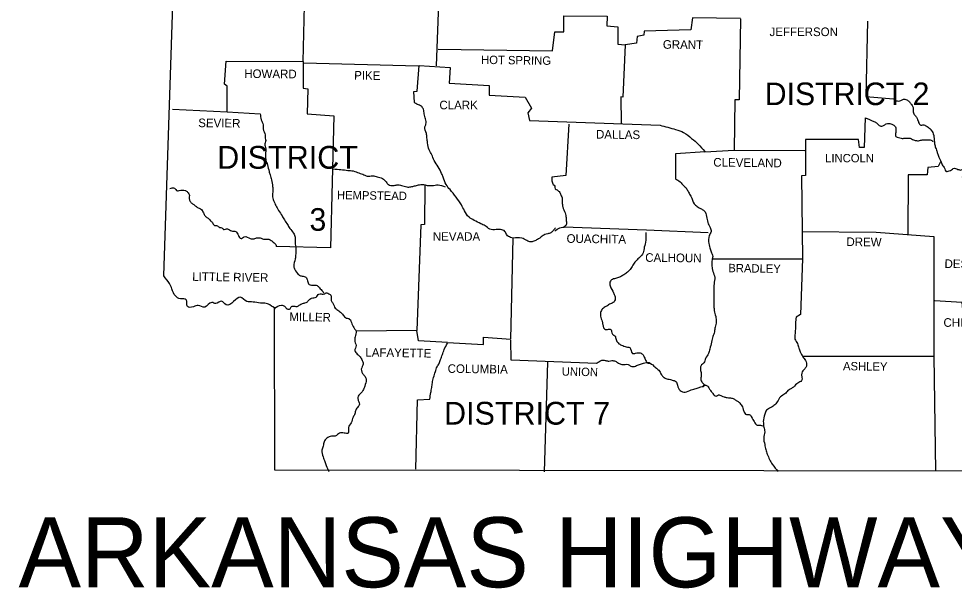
# Model space of a CAD drawing. Extents: x 1096785 to 1382432, y 216169 to 341661.
# Drawn here: x 1227896 to 1237243, y 280666 to 286360 of the extents above; entities that cross this region are included whole.
import ezdxf

# ---------------------------------------------------------------- set-up
doc = ezdxf.new("R2010")
doc.units = 0
for name, color, linetype in [('1', 7, 'Continuous'), ('21', 7, 'Continuous'), ('3', 7, 'Continuous')]:
    doc.layers.add(name, color=color, linetype=linetype)

msp = doc.modelspace()

# ---------------------------------------------------------------- linework, layer by layer
at = {"layer": '1'}
for points in [[(1229345.2, 283788.3), (1229525.2, 289214.3), (1229111.2, 292538.3)], [(1232071.2, 285890.3), (1232117.2, 287136.3)], [(1229431.2, 285454.3), (1229977.2, 285430.3), (1229979.2, 285686.3), (1229951.2, 285706.3), (1229969.2, 285934.3), (1230739.2, 285932.3), (1230761.2, 286916.3)], [(1232085.2, 286056.3), (1233229.2, 286040.3), (1233251.2, 286230.3), (1233341.2, 286230.3), (1233343.2, 286390.3), (1233775.2, 286384.3), (1233771.2, 286288.3), (1233883.2, 286280.3), (1233883.2, 286104.3), (1233955.2, 286098.3)], [(1235107.2, 286362.3), (1234629.2, 286370.3), (1234611.2, 286248.3), (1234145.2, 286234.3), (1234141.2, 286194.3), (1234075.2, 286182.3), (1234067.2, 286114.3), (1233955.2, 286098.3)], [(1235107.2, 286358.3), (1235095.2, 285550.3), (1235049.2, 285548.3), (1235043.2, 285046.3)], [(1236375.2, 286336.3), (1236359.2, 285582.3), (1236637.2, 285560.3)], [(1233955.2, 286098.3), (1233931.2, 285574.3), (1233913.2, 285580.3), (1233915.2, 285308.3)], [(1230739.2, 285932.3), (1230739.2, 285666.3), (1230783.2, 285658.3), (1230779.2, 285410.3), (1231043.2, 285390.3), (1231011.2, 284068.3), (1230467.2, 284082.3)], [(1230743.2, 285918.3), (1231887.2, 285888.3)], [(1231849.2, 285522.3), (1231845.2, 285632.3), (1231877.2, 285634.3), (1231897.2, 285892.3), (1232205.2, 285872.3), (1232197.2, 285714.3), (1232595.2, 285692.3), (1232597.2, 285596.3), (1232957.2, 285574.3), (1233019.2, 285466.3), (1232981.2, 285418.3), (1232999.2, 285344.3), (1234303.2, 285296.3)], [(1229977.2, 285430.3), (1230309.2, 285410.3)], [(1236353.2, 285368.3), (1236341.2, 285074.3), (1236295.2, 285074.3), (1236287.2, 285152.3), (1235755.2, 285152.3), (1235755.2, 285040.3)], [(1233391.2, 285306.3), (1233361.2, 284792.3), (1233223.2, 284776.3)], [(1234755.2, 285028.3), (1234459.2, 285010.3), (1234457.2, 284760.3)], [(1234751.2, 285028.3), (1235043.2, 285046.3)], [(1235043.2, 285046.3), (1235751.2, 285042.3)], [(1235755.2, 285042.3), (1235757.2, 284792.3), (1235715.2, 284790.3), (1235727.2, 283960.3)], [(1237107.2, 284936.3), (1237083.2, 284882.3), (1236977.2, 284872.3), (1236971.2, 284800.3), (1236781.2, 284800.3), (1236779.2, 284202.3)], [(1231955.2, 284700.3), (1231951.2, 284302.3), (1231915.2, 284298.3), (1231875.2, 283244.3)], [(1233341.2, 284278.3), (1234169.2, 284248.3), (1234783.2, 284224.3)], [(1232179.2, 283124.3), (1232539.2, 283102.3), (1232541.2, 283176.3), (1232811.2, 283158.3), (1232837.2, 284166.3)], [(1235721.2, 284232.3), (1236463.2, 284226.3), (1237039.2, 284182.3)], [(1237039.2, 284182.3), (1237039.2, 282986.3), (1237055.2, 281836.3)], [(1234823.2, 283958.3), (1235727.2, 283960.3)], [(1235727.2, 283960.3), (1235707.2, 283404.3), (1235663.2, 283376.3)], [(1237049.2, 283544.3), (1237317.2, 283528.3), (1237329.2, 283412.3), (1237571.2, 283420.3), (1237581.2, 283518.3), (1237627.2, 283518.3)], [(1237785.2, 281836.3), (1230455.2, 281848.3), (1230451.2, 283466.3)], [(1232179.2, 283124.3), (1231889.2, 283140.3), (1231875.2, 283244.3), (1231269.2, 283238.3)], [(1233669.2, 282914.3), (1232815.2, 282946.3), (1232811.2, 283148.3)], [(1235727.2, 282988.3), (1237039.2, 282988.3)], [(1233179.2, 282928.3), (1233147.2, 281830.3)], [(1231865.2, 281858.3), (1231879.2, 282550.3), (1232003.2, 282558.3)]]:
    msp.add_lwpolyline(points, dxfattribs=at)
for points in [[(1236637.2, 285560.3), (1236667.2, 285540.3), (1236709.2, 285542.3), (1236737.2, 285554.3), (1236759.2, 285552.3), (1236789.2, 285534.3), (1236809.2, 285510.3), (1236823.2, 285492.3), (1236833.2, 285464.3), (1236833.2, 285438.3), (1236843.2, 285402.3), (1236855.2, 285388.3), (1236871.2, 285362.3), (1236881.2, 285338.3), (1236887.2, 285322.3), (1236909.2, 285296.3), (1236929.2, 285298.3), (1236947.2, 285296.3), (1236971.2, 285282.3), (1237007.2, 285254.3), (1237013.2, 285246.3), (1237037.2, 285194.3), (1237041.2, 285162.3), (1237045.2, 285120.3), (1237053.2, 285080.3), (1237069.2, 285036.3), (1237077.2, 285006.3), (1237095.2, 284964.3), (1237107.2, 284936.3), (1237123.2, 284900.3), (1237147.2, 284860.3), (1237157.2, 284836.3), (1237191.2, 284838.3), (1237215.2, 284848.3), (1237233.2, 284864.3), (1237255.2, 284862.3), (1237279.2, 284854.3), (1237311.2, 284848.3), (1237331.2, 284860.3), (1237341.2, 284868.3), (1237343.2, 284886.3), (1237361.2, 284896.3), (1237381.2, 284882.3), (1237403.2, 284850.3), (1237403.2, 284830.3), (1237395.2, 284818.3), (1237369.2, 284802.3), (1237333.2, 284790.3), (1237323.2, 284776.3), (1237357.2, 284760.3), (1237411.2, 284756.3), (1237425.2, 284768.3), (1237461.2, 284758.3), (1237475.2, 284768.3), (1237523.2, 284766.3), (1237545.2, 284782.3), (1237589.2, 284780.3), (1237603.2, 284770.3), (1237603.2, 284752.3), (1237639.2, 284744.3), (1237665.2, 284750.3), (1237699.2, 284740.3), (1237729.2, 284724.3), (1237745.2, 284702.3), (1237765.2, 284678.3), (1237783.2, 284684.3), (1237797.2, 284702.3), (1237827.2, 284734.3), (1237827.2, 284754.3), (1237835.2, 284768.3), (1237845.2, 284788.3)], [(1232837.2, 284166.3), (1232809.2, 284174.3), (1232773.2, 284198.3), (1232753.2, 284234.3), (1232711.2, 284252.3), (1232665.2, 284252.3), (1232603.2, 284256.3), (1232555.2, 284290.3), (1232513.2, 284310.3), (1232447.2, 284344.3), (1232395.2, 284376.3), (1232349.2, 284440.3), (1232319.2, 284498.3), (1232265.2, 284576.3), (1232205.2, 284652.3), (1232167.2, 284702.3), (1232137.2, 284776.3), (1232121.2, 284812.3), (1232087.2, 284880.3), (1232047.2, 284942.3), (1232023.2, 285000.3), (1231997.2, 285048.3), (1231981.2, 285118.3), (1231975.2, 285170.3), (1231969.2, 285214.3), (1231953.2, 285278.3), (1231965.2, 285306.3), (1231961.2, 285358.3), (1231947.2, 285408.3), (1231939.2, 285454.3), (1231919.2, 285484.3), (1231881.2, 285502.3), (1231849.2, 285522.3)], [(1230309.2, 285410.3), (1230319.2, 285350.3), (1230337.2, 285298.3), (1230339.2, 285258.3), (1230357.2, 285198.3), (1230357.2, 285176.3), (1230363.2, 285132.3), (1230355.2, 285108.3), (1230365.2, 285060.3), (1230363.2, 285024.3), (1230363.2, 284994.3), (1230365.2, 284944.3), (1230381.2, 284900.3), (1230397.2, 284834.3), (1230407.2, 284800.3), (1230423.2, 284748.3), (1230433.2, 284684.3), (1230435.2, 284636.3), (1230431.2, 284592.3), (1230443.2, 284542.3), (1230465.2, 284492.3), (1230493.2, 284444.3), (1230527.2, 284390.3), (1230551.2, 284348.3), (1230581.2, 284302.3), (1230605.2, 284264.3), (1230641.2, 284216.3), (1230657.2, 284176.3), (1230657.2, 284120.3), (1230665.2, 284068.3), (1230663.2, 284010.3), (1230659.2, 283958.3), (1230645.2, 283886.3), (1230655.2, 283852.3), (1230693.2, 283802.3), (1230717.2, 283788.3), (1230759.2, 283780.3), (1230779.2, 283752.3), (1230791.2, 283710.3), (1230833.2, 283696.3), (1230879.2, 283692.3), (1230901.2, 283668.3), (1230931.2, 283636.3), (1230941.2, 283620.3)], [(1236353.2, 285368.3), (1236389.2, 285356.3), (1236415.2, 285342.3), (1236449.2, 285330.3), (1236471.2, 285314.3), (1236501.2, 285288.3), (1236537.2, 285292.3), (1236563.2, 285308.3), (1236589.2, 285312.3), (1236609.2, 285310.3), (1236631.2, 285298.3), (1236655.2, 285280.3), (1236659.2, 285254.3), (1236659.2, 285224.3), (1236659.2, 285182.3), (1236673.2, 285176.3), (1236723.2, 285164.3), (1236757.2, 285166.3), (1236789.2, 285166.3), (1236815.2, 285160.3), (1236837.2, 285148.3), (1236853.2, 285144.3), (1236877.2, 285140.3), (1236897.2, 285142.3), (1236931.2, 285150.3), (1236951.2, 285150.3), (1236983.2, 285150.3), (1237003.2, 285148.3), (1237033.2, 285132.3)], [(1234303.2, 285296.3), (1234459.2, 285252.3), (1234539.2, 285222.3), (1234619.2, 285164.3), (1234685.2, 285106.3), (1234751.2, 285032.3)], [(1231039.2, 284858.3), (1231115.2, 284852.3), (1231185.2, 284844.3), (1231239.2, 284838.3), (1231295.2, 284818.3), (1231345.2, 284800.3), (1231377.2, 284786.3), (1231431.2, 284790.3), (1231477.2, 284780.3), (1231529.2, 284762.3), (1231567.2, 284728.3), (1231591.2, 284702.3), (1231637.2, 284692.3), (1231675.2, 284698.3), (1231721.2, 284694.3), (1231773.2, 284678.3), (1231815.2, 284680.3), (1231849.2, 284688.3), (1231889.2, 284698.3), (1231939.2, 284702.3), (1231977.2, 284694.3), (1232027.2, 284692.3), (1232085.2, 284698.3), (1232157.2, 284678.3)], [(1233223.2, 284776.3), (1233223.2, 284738.3), (1233237.2, 284702.3), (1233251.2, 284686.3), (1233257.2, 284660.3), (1233275.2, 284648.3), (1233301.2, 284624.3), (1233315.2, 284590.3), (1233325.2, 284568.3), (1233325.2, 284540.3), (1233327.2, 284512.3), (1233331.2, 284478.3), (1233355.2, 284418.3), (1233361.2, 284394.3), (1233365.2, 284374.3), (1233367.2, 284340.3), (1233367.2, 284300.3), (1233341.2, 284278.3)], [(1234457.2, 284760.3), (1234503.2, 284730.3), (1234541.2, 284690.3), (1234569.2, 284660.3), (1234587.2, 284626.3), (1234611.2, 284586.3), (1234645.2, 284510.3), (1234675.2, 284484.3), (1234717.2, 284458.3), (1234743.2, 284440.3), (1234769.2, 284382.3), (1234781.2, 284324.3), (1234803.2, 284272.3), (1234813.2, 284232.3), (1234795.2, 284192.3), (1234791.2, 284112.3), (1234803.2, 284058.3), (1234819.2, 284018.3), (1234829.2, 283972.3), (1234823.2, 283958.3)], [(1229407.2, 284664.3), (1229451.2, 284666.3), (1229481.2, 284640.3), (1229499.2, 284642.3), (1229531.2, 284646.3), (1229561.2, 284644.3), (1229583.2, 284626.3), (1229601.2, 284594.3), (1229599.2, 284564.3), (1229601.2, 284552.3), (1229615.2, 284526.3), (1229639.2, 284506.3), (1229665.2, 284486.3), (1229689.2, 284470.3), (1229729.2, 284444.3), (1229733.2, 284436.3), (1229749.2, 284404.3), (1229769.2, 284378.3), (1229793.2, 284362.3), (1229819.2, 284334.3), (1229831.2, 284322.3), (1229851.2, 284294.3), (1229873.2, 284292.3), (1229903.2, 284274.3), (1229925.2, 284268.3), (1229949.2, 284252.3), (1229973.2, 284260.3), (1230003.2, 284248.3), (1230043.2, 284236.3), (1230065.2, 284232.3), (1230091.2, 284194.3), (1230117.2, 284162.3), (1230149.2, 284180.3), (1230209.2, 284162.3), (1230247.2, 284160.3), (1230281.2, 284170.3), (1230307.2, 284168.3), (1230355.2, 284156.3), (1230385.2, 284156.3), (1230417.2, 284144.3), (1230447.2, 284120.3), (1230467.2, 284094.3), (1230467.2, 284082.3)], [(1233259.2, 284268.3), (1233237.2, 284242.3), (1233211.2, 284220.3), (1233181.2, 284210.3), (1233153.2, 284202.3), (1233117.2, 284178.3), (1233089.2, 284158.3), (1233051.2, 284140.3), (1233015.2, 284128.3), (1232971.2, 284142.3), (1232947.2, 284156.3), (1232921.2, 284166.3), (1232837.2, 284166.3)], [(1233251.2, 284236.3), (1233303.2, 284270.3), (1233361.2, 284278.3)], [(1234161.2, 284224.3), (1234157.2, 284124.3), (1234143.2, 284062.3), (1234129.2, 284006.3), (1234099.2, 283974.3), (1234067.2, 283942.3), (1234037.2, 283906.3), (1234011.2, 283862.3), (1233985.2, 283834.3), (1233951.2, 283806.3), (1233917.2, 283786.3), (1233879.2, 283768.3), (1233837.2, 283758.3), (1233807.2, 283736.3), (1233805.2, 283688.3), (1233839.2, 283620.3), (1233851.2, 283588.3), (1233855.2, 283550.3), (1233841.2, 283528.3), (1233809.2, 283510.3), (1233771.2, 283488.3), (1233737.2, 283468.3), (1233713.2, 283434.3), (1233709.2, 283388.3), (1233725.2, 283334.3), (1233731.2, 283302.3), (1233757.2, 283252.3), (1233777.2, 283254.3), (1233813.2, 283252.3), (1233817.2, 283242.3), (1233819.2, 283232.3), (1233827.2, 283206.3), (1233857.2, 283184.3), (1233861.2, 283164.3), (1233879.2, 283126.3), (1233909.2, 283100.3), (1233931.2, 283092.3), (1233977.2, 283078.3), (1234001.2, 283072.3), (1234027.2, 283014.3), (1234059.2, 283016.3), (1234083.2, 283020.3), (1234123.2, 283010.3), (1234141.2, 282986.3), (1234159.2, 282946.3), (1234183.2, 282918.3), (1234199.2, 282918.3)], [(1234823.2, 283958.3), (1234831.2, 283834.3), (1234849.2, 283774.3), (1234843.2, 283710.3), (1234841.2, 283648.3), (1234841.2, 283592.3), (1234841.2, 283538.3), (1234841.2, 283482.3), (1234845.2, 283442.3), (1234859.2, 283384.3), (1234865.2, 283330.3), (1234853.2, 283278.3), (1234847.2, 283230.3), (1234831.2, 283182.3), (1234817.2, 283128.3), (1234801.2, 283058.3), (1234787.2, 283012.3), (1234759.2, 282964.3), (1234741.2, 282920.3), (1234713.2, 282892.3), (1234709.2, 282844.3), (1234715.2, 282800.3), (1234711.2, 282760.3), (1234725.2, 282722.3), (1234761.2, 282696.3)], [(1230451.2, 283466.3), (1230459.2, 283462.3), (1230421.2, 283488.3), (1230369.2, 283514.3), (1230311.2, 283518.3), (1230237.2, 283528.3), (1230175.2, 283534.3), (1230111.2, 283576.3), (1230043.2, 283532.3), (1229967.2, 283500.3), (1229923.2, 283536.3), (1229865.2, 283512.3), (1229825.2, 283524.3), (1229755.2, 283476.3), (1229689.2, 283494.3), (1229641.2, 283480.3), (1229581.2, 283482.3), (1229569.2, 283550.3), (1229511.2, 283560.3), (1229461.2, 283588.3), (1229427.2, 283658.3), (1229403.2, 283712.3), (1229345.2, 283788.3)], [(1230451.2, 283466.3), (1230521.2, 283496.3), (1230551.2, 283486.3), (1230577.2, 283460.3), (1230607.2, 283460.3), (1230623.2, 283484.3), (1230653.2, 283486.3), (1230677.2, 283484.3), (1230703.2, 283500.3), (1230725.2, 283510.3), (1230755.2, 283520.3), (1230777.2, 283528.3), (1230797.2, 283550.3), (1230833.2, 283568.3), (1230875.2, 283582.3), (1230887.2, 283602.3), (1230907.2, 283610.3), (1230947.2, 283608.3), (1230973.2, 283620.3), (1230995.2, 283610.3), (1231015.2, 283596.3), (1231019.2, 283544.3), (1231035.2, 283516.3), (1231059.2, 283466.3), (1231093.2, 283440.3), (1231125.2, 283414.3), (1231137.2, 283398.3), (1231171.2, 283368.3), (1231201.2, 283358.3), (1231215.2, 283336.3), (1231237.2, 283284.3), (1231269.2, 283238.3)], [(1235663.2, 283376.3), (1235657.2, 283314.3), (1235655.2, 283256.3), (1235651.2, 283200.3), (1235651.2, 283158.3), (1235675.2, 283112.3), (1235689.2, 283068.3), (1235703.2, 283030.3), (1235731.2, 282980.3), (1235757.2, 282942.3), (1235765.2, 282888.3), (1235749.2, 282860.3), (1235719.2, 282818.3), (1235717.2, 282742.3), (1235681.2, 282718.3), (1235635.2, 282678.3), (1235609.2, 282660.3), (1235581.2, 282642.3), (1235551.2, 282610.3), (1235507.2, 282580.3), (1235475.2, 282530.3), (1235439.2, 282492.3), (1235409.2, 282472.3), (1235367.2, 282446.3), (1235349.2, 282406.3), (1235335.2, 282332.3), (1235341.2, 282278.3), (1235349.2, 282230.3), (1235339.2, 282170.3), (1235349.2, 282104.3), (1235359.2, 282052.3), (1235375.2, 282006.3), (1235397.2, 281954.3), (1235425.2, 281906.3), (1235485.2, 281832.3)], [(1231269.2, 283238.3), (1231257.2, 283180.3), (1231255.2, 283134.3), (1231265.2, 283080.3), (1231255.2, 283054.3), (1231271.2, 283016.3), (1231301.2, 282986.3), (1231323.2, 282954.3), (1231337.2, 282908.3), (1231319.2, 282856.3), (1231339.2, 282802.3), (1231357.2, 282782.3), (1231367.2, 282750.3), (1231353.2, 282688.3), (1231335.2, 282642.3), (1231295.2, 282596.3), (1231283.2, 282574.3), (1231289.2, 282544.3), (1231299.2, 282496.3), (1231289.2, 282482.3), (1231263.2, 282448.3), (1231255.2, 282410.3), (1231237.2, 282378.3), (1231217.2, 282320.3), (1231191.2, 282272.3), (1231187.2, 282218.3), (1231147.2, 282218.3), (1231101.2, 282218.3), (1231059.2, 282188.3), (1231021.2, 282186.3), (1230975.2, 282168.3), (1230947.2, 282130.3), (1230937.2, 282088.3), (1230925.2, 282048.3), (1230937.2, 281980.3), (1230955.2, 281932.3), (1230969.2, 281894.3), (1230993.2, 281832.3)], [(1232003.2, 282558.3), (1232013.2, 282622.3), (1232023.2, 282672.3), (1232029.2, 282720.3), (1232041.2, 282774.3), (1232059.2, 282832.3), (1232075.2, 282880.3), (1232097.2, 282914.3), (1232111.2, 282954.3), (1232129.2, 283002.3), (1232147.2, 283052.3), (1232179.2, 283116.3)], [(1233669.2, 282914.3), (1233701.2, 282936.3), (1233731.2, 282948.3), (1233761.2, 282942.3), (1233793.2, 282938.3), (1233821.2, 282942.3), (1233857.2, 282936.3), (1233887.2, 282918.3), (1233921.2, 282904.3), (1233955.2, 282904.3), (1233985.2, 282904.3), (1234011.2, 282886.3), (1234059.2, 282888.3), (1234099.2, 282904.3), (1234139.2, 282916.3), (1234193.2, 282922.3), (1234241.2, 282888.3), (1234275.2, 282860.3), (1234303.2, 282828.3), (1234323.2, 282792.3), (1234345.2, 282772.3), (1234381.2, 282758.3), (1234409.2, 282752.3), (1234443.2, 282742.3), (1234461.2, 282734.3), (1234477.2, 282696.3), (1234503.2, 282644.3), (1234553.2, 282626.3), (1234615.2, 282650.3), (1234665.2, 282664.3), (1234701.2, 282676.3), (1234723.2, 282684.3), (1234743.2, 282686.3), (1234737.2, 282690.3), (1234761.2, 282696.3), (1234783.2, 282680.3), (1234797.2, 282658.3), (1234821.2, 282626.3), (1234843.2, 282598.3), (1234865.2, 282588.3), (1234887.2, 282600.3), (1234917.2, 282590.3), (1234943.2, 282580.3), (1234973.2, 282572.3), (1234999.2, 282570.3), (1235033.2, 282562.3), (1235059.2, 282548.3), (1235083.2, 282534.3), (1235107.2, 282508.3), (1235131.2, 282468.3), (1235139.2, 282436.3), (1235167.2, 282404.3), (1235193.2, 282404.3), (1235231.2, 282352.3), (1235245.2, 282332.3), (1235275.2, 282296.3), (1235297.2, 282296.3), (1235339.2, 282288.3)]]:
    msp.add_spline(points, degree=3, dxfattribs=at)

# ---------------------------------------------------------------- texts
at = {"layer": '21'}
msp.add_text('PIKE', height=85.99, rotation=359.04516, dxfattribs=at).set_placement((1231247.2, 285752.3))
for s, height, p in [('DISTRICT 2', 226, (1235349.2, 285496.3)), ('DISTRICT', 228, (1229879.2, 284860.3)), ('3', 226, (1230801.2, 284240.3)), ('DISTRICT 7', 228, (1232145.2, 282302.3))]:
    msp.add_text(s, height=height, dxfattribs=at).set_placement(p)
at = {"layer": '3'}
for s, height, p in [('JEFFERSON', 86, (1235397.2, 286186.3)), ('CLARK', 86, (1232099.2, 285454.3)), ('LINCOLN', 84, (1235953.2, 284924.3)), ('NEVADA', 86, (1232033.2, 284140.3)), ('CHICOT', 86, (1237135.2, 283280.3)), ('ARKANSAS HIGHWAY DISTRICT 6', 699.996, (1227894.4, 280676.3))]:
    msp.add_text(s, height=height, dxfattribs=at).set_placement(p)
for s, height, rotation, p in [('GRANT', 86.02, 359.40319, (1234331.2, 286060.3)), ('HOT SPRING', 84.01, 359.22157, (1232515.2, 285908.3)), ('HOWARD', 86.02, 359.51446, (1230149.2, 285768.3)), ('SEVIER', 86.02, 359.42706, (1229689.2, 285276.3)), ('DALLAS', 85.99, 359.24615, (1233663.2, 285162.3)), ('CLEVELAND', 86.02, 359.33765, (1234835.2, 284882.3)), ('HEMPSTEAD', 83.99, 359.1885, (1231075.2, 284556.3)), ('OUACHITA', 86.02, 359.20428, (1233369.2, 284120.3)), ('DREW', 85.99, 359.22578, (1236165.2, 284088.3)), ('CALHOUN', 86.02, 359.36341, (1234155.2, 283930.3)), ('BRADLEY', 83.99, 359.1449, (1234985.2, 283826.3)), ('DESHA', 85.99, 359.3704, (1237145.2, 283868.3)), ('LITTLE RIVER', 86.016, 359.16968, (1229629.2, 283740.3)), ('MILLER', 85.99, 359.13195, (1230599.2, 283338.3)), ('LAFAYETTE', 85.99, 359.18388, (1231359.2, 282982.3)), ('ASHLEY', 84.01, 359.2361, (1236131.2, 282846.3)), ('COLUMBIA', 85.99, 359.21248, (1232181.2, 282820.3)), ('UNION', 84.01, 358.95837, (1233321.2, 282792.3))]:
    msp.add_text(s, height=height, rotation=rotation, dxfattribs=at).set_placement(p)

doc.saveas('drawing.dxf')
